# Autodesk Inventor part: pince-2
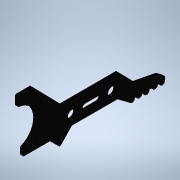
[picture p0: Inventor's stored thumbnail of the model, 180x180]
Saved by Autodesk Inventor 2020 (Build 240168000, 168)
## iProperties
Created: 2021-10
Part Number: pince-2
Material: Générique
Document SubType Name: Modeling
Designer: bruno
Density: 1 g/cm^3
Appearance: Noir
Author: bruno
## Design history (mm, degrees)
sketch "Esquisse1"
  geometry: L1 (-4.155, -25.629)-(-4.155, -30.629); L2 (-6.155, -25.629)-(-6.155, -30.629); L3 (7.691, -0.438)-(10.446, -0.438); L4 (-7.207, -2.346)-(-9.233, -2.346); L5 (8.1, -6.586)-(8.1, -6.58); L6 (-11.258, -0.35)-(-11.258, -0.438); L7 (-0.354, -38.146)-(-0.354, -17.123); L8 (-9.733, -12.473)-(-13.092, -15.878); L9 (-6.724, -44.413)-(-8.393, -53.057); L10 (-8.393, -53.057)-(-10.196, -55.455); L11 (-10.196, -55.455)-(-11.607, -55.455); L12 (-12.297, -55.455)-(-12.297, -55.165); L13 (-11.588, -44.203)-(-11.588, -44.904); L14 (-13.08, -16.591)-(-8.776, -20.676); L15 (-8.776, -20.676)-(-8.776, -37.72); L16 (-11.607, -52.755)-(-11.607, -53.455); L17 (-11.596, -46.903)-(-11.596, -47.627); L18 (-11.596, -49.577)-(-11.596, -50.755); L19 (-11.588, -43.757)-(-11.596, -43.741); L20 (-4.7, -24.661)-(-4.7, -29.925); L21 (-0.354, -38.146)-(-0.354, -38.16); L22 (-9.733, -12.473)-(-9.733, -5.167); L23 (10.946, -6.1)-(-0.354, -17.123); L24 (10.946, -4.623)-(10.946, -6.1); L25 (-9.733, -5.167)-(-9.733, -2.846); L26 (-11.607, -54.455)-(-11.207, -54.455); L27 (-0.354, -38.16)-(-6.724, -44.413); L28 (-8.776, -37.72)-(-12.453, -42.615); L29 (-11.588, -14.346)-(-11.596, -14.356); L30 (-13.055, -16.614)-(-13.055, -16.615); L31 (10.946, -4.623)-(10.946, -0.938); C1 r 1.75 at (-5.176, -35.629); C2 r 1.75 at (-5.176, -20.629); A1 r 1 centre (-5.155, -30.629) between (-6.155, -30.629) and (-4.155, -30.629); A2 r 1 centre (-5.155, -25.629) between (-4.155, -25.629) and (-6.155, -25.629); A3 r 7.248 centre (0, 0) between (-6.742, -2.662) and (7.195, -0.878); A4 r 0.5 centre (7.691, -0.938) between (7.691, -0.438) and (7.195, -0.878); A5 r 0.5 centre (-7.207, -2.846) between (-6.742, -2.662) and (-7.207, -2.346); A6 r 1 centre (-11.646, -43.205) between (-12.453, -42.615) and (-11.588, -44.203); A7 r 1 centre (-11.562, -45.904) between (-11.588, -44.904) and (-11.596, -46.903); A8 r 1 centre (-11.818, -48.602) between (-11.596, -47.627) and (-11.596, -49.577); A9 r 1 centre (-11.607, -51.755) between (-11.596, -50.755) and (-11.607, -52.755); A10 r 1 centre (-11.607, -54.455) between (-11.607, -53.455) and (-11.607, -55.455); A11 r 0.5 centre (-12.736, -16.229) between (-13.092, -15.878) and (-13.08, -16.591); A12 r 10.964 centre (0, 0) between (-10.953, -0.495) and (-10.951, -0.523); A13 r 0.5 centre (-10.233, -4.159) between (-9.926, -3.764) and (-9.93, -3.761); A14 r 0.5 centre (-9.233, -2.846) between (-9.233, -2.346) and (-9.733, -2.846); A15 r 10.961 centre (0, 0) between (-10.953, -0.418) and (-10.952, -0.438); A16 r 0.5 centre (10.446, -0.938) between (10.946, -0.938) and (10.446, -0.438); 26 further points
  constraints: 64 end point, 34 point on circle, 18 centre point, 13 point on line, 12 tangent, 9 vertical, 5 coincident, 4 perpendicular, 3 horizontal, 2 parallel, 1 midpoint
  dimensions: "d44" = 2 diameter of A1; "d45" = 2 diameter of A2; "d46" = 5 distance of A1.centre A2.centre; "d67" = 12 distance from line of L4 L29.start; "d81" = 3 distance of L9.end L10.end; "d83" = 2 diameter of A7; "d84" = 2 diameter of A6; "d85" = 2 diameter of A8; "d86" = 2 diameter of A9; "d87" = 2.7 distance of A6.centre A7.centre; "d107" = 0.4 distance of L26.start L26.end; "d108" = 3.5 diameter of C1; "d109" = 3.5 diameter of C2; "d110" = 3.6 distance from line of C1.centre L15; "d111" = 3.6 distance from line of L15 C2.centre; "d112" = 15 distance of C2.centre C1.centre; "d113" = 5 vertical distance of A2.centre C2.centre; "d114" = 0.5 radius of A16
extrude "Extrusion4" new body sketch "Esquisse1" distance "d70" = 1; taper "d71" = 0 deg
sketch "Esquisse3"
  geometry: C1 r 1.5 at (-35.666, -5.176) reference; C2 r 1.5 at (-20.67, -5.171) reference; C3 r 1.5 at (-35.666, -5.176) reference; 1 further point
extrude "Extrusion5" cut sketch "Esquisse3" distance "d115" = 10; taper "d116" = 0 deg
node "Solide2"
node "Référence1"
node "Référence2"
node "Référence3"
other parameters: "d5" = 22.5, "d76" = 5, "d78" = 3.5, "d99" = 0.5 (derived), "d100" = 0.5 (derived)
